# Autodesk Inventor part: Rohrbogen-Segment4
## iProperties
Created: 2006-10
Part Number: Rohrbogen-Segment4
Cost Center: 4,74 kg
Material: 1.4301 (X5CrNi18 10)
Document SubType Name: Sheet Metal
Designer: grote
Authority: 592367,5 mm^3
Manufacturer: Standard
Standards Organization: Custom
Objekthöhe: 10,000 mm
SaveDate: 2006-10-11
SaveTime: 08:22
FileName: Rohrbogen-Segment4
TotalMass: 4,74 kg
TotalVolume: 592367,5 mm^3
SM_Thickness: 10 mm
SM_Style: NIRO-V80(t =4-10 mm)
SM_Extents: 315,418 mm x 378,344 mm
SM_Square: 119336 mm²
SM_Extents_Width: 315,418 mm
SM_Extents_Length: 378,344 mm
Author: grote
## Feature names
1. Trennen1
2. Trennen2
3. Abgeleiteter Körper1 [Tagging]
4. ExtrusionAbwicklung1
